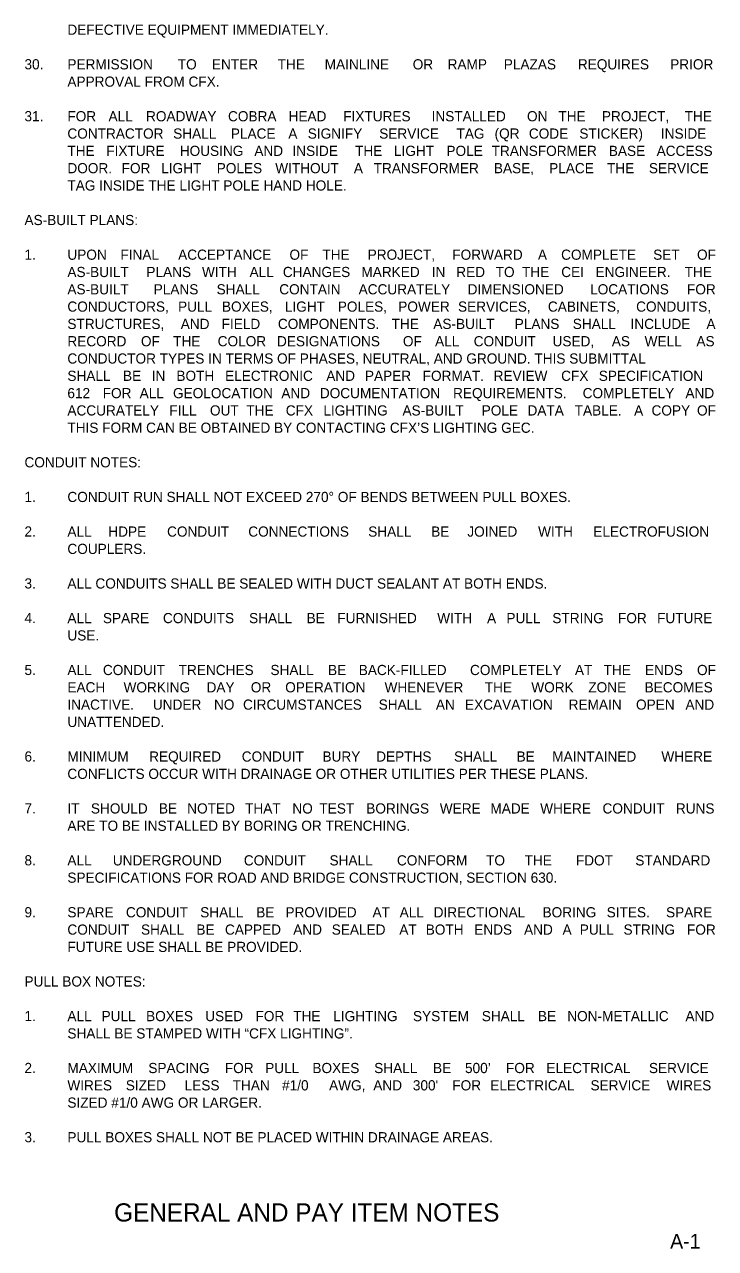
# Model space of a CAD drawing. Extents: x -55 to 2471539, y -90 to 3608906.
# Drawn here: x 1052 to 1526, y -64 to 777 of the extents above; entities that cross this region are included whole.
import ezdxf

# ---------------------------------------------------------------- set-up
doc = ezdxf.new("R2010")
doc.units = 0
for name, color, linetype in [('SheetLines_dp', 7, 'Continuous'), ('TextMisc', 7, 'Continuous'), ('XSCell', 7, 'Continuous')]:
    doc.layers.add(name, color=color, linetype=linetype)

msp = doc.modelspace()

# ---------------------------------------------------------------- texts
at = {"layer": 'SheetLines_dp'}
msp.add_text('A-1', height=10, dxfattribs=at).set_placement((1495.16, -64.49))
at = {"layer": 'TextMisc'}
msp.add_text('GENERAL AND PAY ITEM NOTES ', height=12.5, dxfattribs=at).set_placement((1113.09, -45.92))
at = {"layer": 'XSCell'}
for s, p in [('DEFECTIVE EQUIPMENT IMMEDIATELY.', (1080.99, 770.14)), ('30.', (1051.5, 746.38)), ('PERMISSION ', (1080.99, 746.34)), ('TO ', (1156.84, 746.34)), ('ENTER ', (1180.3, 746.34)), ('THE ', (1225.48, 746.34)), ('MAINLINE ', (1257.78, 746.34)), ('OR ', (1318.26, 746.34)), ('RAMP ', (1342.22, 746.34)), ('PLAZAS ', (1380.82, 746.34)), ('REQUIRES ', (1431.73, 746.34)), ('PRIOR ', (1495.16, 746.34)), ('APPROVAL FROM CFX.', (1080.99, 734.44)), ('31.', (1051.5, 710.68)), ('FOR ', (1080.99, 710.64)), ('ALL ', (1109.24, 710.64)), ('ROADWAY ', (1135.03, 710.64)), ('COBRA ', (1191.36, 710.64)), ('HEAD ', (1232.94, 710.64)), ('FIXTURES ', (1270.52, 710.64)), ('INSTALLED ', (1331.24, 710.64)), ('ON ', (1396.78, 710.64)), ('THE ', (1418.36, 710.64)), ('PROJECT, ', (1448.22, 710.64)), ('THE ', (1505.1, 710.64)), ('CONTRACTOR ', (1080.99, 698.74)), ('SHALL ', (1153.67, 698.74)), ('PLACE ', (1193.29, 698.74)), ('A ', (1232.77, 698.74)), ('SIGNIFY ', (1246.14, 698.74)), ('SERVICE ', (1295.23, 698.74)), ('TAG ', (1348.34, 698.74)), ('(QR ', (1374.5, 698.74)), ('CODE ', (1398.05, 698.74)), ('STICKER) ', (1432.76, 698.74)), ('INSIDE ', (1488.78, 698.74)), ('THE ', (1080.99, 686.84)), ('FIXTURE ', (1107.71, 686.84)), ('HOUSING ', (1158.21, 686.84)), ('AND ', (1209.44, 686.84)), ('INSIDE ', (1235.62, 686.84)), ('THE ', (1278.65, 686.84)), ('LIGHT ', (1305.37, 686.84)), ('POLE ', (1341.43, 686.84)), ('TRANSFORMER ', (1372.49, 686.84)), ('BASE ', (1453, 686.84)), ('ACCESS ', (1485.85, 686.84)), ('DOOR. ', (1080.99, 674.94)), ('FOR ', (1118.27, 674.94)), ('LIGHT ', (1145.44, 674.94)), ('POLES ', (1183.59, 674.94)), ('WITHOUT ', (1223.8, 674.94)), ('A ', (1277.8, 674.94)), ('TRANSFORMER ', (1291.42, 674.94)), ('BASE, ', (1374.02, 674.94)), ('PLACE ', (1412, 674.94)), ('THE ', (1451.74, 674.94)), ('SERVICE ', (1480.54, 674.94)), ('TAG INSIDE THE LIGHT POLE HAND HOLE.', (1080.99, 663.04)), ('AS-BUILT PLANS:', (1051.5, 639.28)), ('1.', (1051.5, 615.48)), ('UPON ', (1080.99, 615.44)), ('FINAL ', (1117.41, 615.44)), ('ACCEPTANCE ', (1157.09, 615.44)), ('OF ', (1233.58, 615.44)), ('THE ', (1256.2, 615.44)), ('PROJECT, ', (1287.31, 615.44)), ('FORWARD ', (1345.45, 615.44)), ('A ', (1404.28, 615.44)), ('COMPLETE ', (1420.22, 615.44)), ('SET ', (1483.47, 615.44)), ('OF ', (1513.59, 615.44)), ('AS-BUILT ', (1080.99, 603.54)), ('PLANS ', (1135.26, 603.54)), ('WITH ', (1173.46, 603.54)), ('ALL ', (1206.16, 603.54)), ('CHANGES ', (1229.03, 603.54)), ('MARKED ', (1283, 603.54)), ('IN ', (1331.35, 603.54)), ('RED ', (1348.18, 603.54)), ('TO ', (1375.25, 603.54)), ('THE ', (1393.35, 603.54)), ('CEI ', (1420.3, 603.54)), ('ENGINEER. ', (1443.89, 603.54)), ('THE ', (1505.1, 603.54)), ('AS-BUILT ', (1080.99, 591.64)), ('PLANS ', (1140.28, 591.64)), ('SHALL ', (1183.52, 591.64)), ('CONTAIN ', (1226.56, 591.64)), ('ACCURATELY ', (1281.08, 591.64)), ('DIMENSIONED ', (1355.99, 591.64)), ('LOCATIONS ', (1440.14, 591.64)), ('FOR ', (1506.71, 591.64)), ('CONDUCTORS, ', (1080.99, 579.74)), ('PULL ', (1157.04, 579.74)), ('BOXES, ', (1187.18, 579.74)), ('LIGHT ', (1230.39, 579.74)), ('POLES, ', (1266.78, 579.74)), ('POWER ', (1308.31, 579.74)), ('SERVICES, ', (1349.37, 579.74)), ('CABINETS, ', (1411.13, 579.74)), ('CONDUITS, ', (1471.76, 579.74)), ('STRUCTURES, ', (1080.99, 567.84)), ('AND ', (1158.87, 567.84)), ('FIELD ', (1186.95, 567.84)), ('COMPONENTS. ', (1225.61, 567.84)), ('THE ', (1303.77, 567.84)), ('AS-BUILT ', (1332.39, 567.84)), ('PLANS ', (1388.33, 567.84)), ('SHALL ', (1428.22, 567.84)), ('INCLUDE ', (1467.92, 567.84)), ('A ', (1520.06, 567.84)), ('RECORD ', (1080.99, 555.94)), ('OF ', (1131.52, 555.94)), ('THE ', (1153.64, 555.94)), ('COLOR ', (1184.25, 555.94)), ('DESIGNATIONS ', (1225, 555.94)), ('OF ', (1311.51, 555.94)), ('ALL ', (1333.62, 555.94)), ('CONDUIT ', (1360.16, 555.94)), ('USED, ', (1414.35, 555.94)), ('AS ', (1455.05, 555.94)), ('WELL ', (1477.57, 555.94)), ('AS ', (1513.18, 555.94)), ('CONDUCTOR TYPES IN TERMS OF PHASES, NEUTRAL, AND GROUND. THIS SUBMITTAL ', (1080.99, 544.04)), ('SHALL ', (1080.99, 532.14)), ('BE ', (1119.17, 532.14)), ('IN ', (1138.91, 532.14)), ('BOTH ', (1155.9, 532.14)), ('ELECTRONIC ', (1189.32, 532.14)), ('AND ', (1258.87, 532.14)), ('PAPER ', (1285.43, 532.14)), ('FORMAT. ', (1325.11, 532.14)), ('REVIEW ', (1373.87, 532.14)), ('CFX ', (1420.25, 532.14)), ('SPECIFICATION ', (1446.08, 532.14)), ('612 ', (1080.99, 520.24)), ('FOR ', (1105.26, 520.24)), ('ALL ', (1130.64, 520.24)), ('GEOLOCATION ', (1153.56, 520.24)), ('AND ', (1227.99, 520.24)), ('DOCUMENTATION ', (1254.44, 520.24)), ('REQUIREMENTS. ', (1345.98, 520.24)), ('COMPLETELY ', (1435.03, 520.24)), ('AND ', (1505.64, 520.24)), ('ACCURATELY ', (1080.99, 508.34)), ('FILL ', (1151.05, 508.34)), ('OUT ', (1178.93, 508.34)), ('THE ', (1203.92, 508.34)), ('CFX ', (1231.04, 508.34)), ('LIGHTING ', (1256.88, 508.34)), ('AS-BUILT ', (1311.22, 508.34)), ('POLE ', (1365.65, 508.34)), ('DATA ', (1397.11, 508.34)), ('TABLE. ', (1429.54, 508.34)), ('A ', (1470.38, 508.34)), ('COPY ', (1482.33, 508.34)), ('OF ', (1513.59, 508.34)), ('THIS FORM CAN BE OBTAINED BY CONTACTING CFX’S LIGHTING GEC.', (1080.99, 496.44)), ('CONDUIT NOTES:', (1051.5, 472.68)), ('1.', (1051.5, 448.88)), ('CONDUIT RUN SHALL NOT EXCEED 270° OF BENDS BETWEEN PULL BOXES.', (1080.99, 448.84)), ('2.', (1051.5, 425.08)), ('ALL ', (1080.99, 425.04)), ('HDPE ', (1109.12, 425.04)), ('CONDUIT ', (1149.48, 425.04)), ('CONNECTIONS ', (1205.26, 425.04)), ('SHALL ', (1287.67, 425.04)), ('BE ', (1330.94, 425.04)), ('JOINED ', (1355.77, 425.04)), ('WITH ', (1404.4, 425.04)), ('ELECTROFUSION ', (1442.34, 425.04)), ('COUPLERS.', (1080.99, 413.14)), ('3.', (1051.5, 389.38)), ('ALL CONDUITS SHALL BE SEALED WITH DUCT SEALANT AT BOTH ENDS.', (1080.99, 389.34)), ('4.', (1051.5, 365.58)), ('ALL ', (1080.99, 365.54)), ('SPARE ', (1105.4, 365.54)), ('CONDUITS ', (1146.66, 365.54)), ('SHALL ', (1205.81, 365.54)), ('BE ', (1245.36, 365.54)), ('FURNISHED ', (1266.47, 365.54)), ('WITH ', (1335.1, 365.54)), ('A ', (1369.33, 365.54)), ('PULL ', (1382.64, 365.54)), ('STRING ', (1414.2, 365.54)), ('FOR ', (1459.3, 365.54)), ('FUTURE ', (1486.16, 365.54)), ('USE.', (1080.99, 353.64)), ('5.', (1051.5, 329.88)), ('ALL ', (1080.99, 329.84)), ('CONDUIT ', (1105.4, 329.84)), ('TRENCHES ', (1157.46, 329.84)), ('SHALL ', (1220.52, 329.84)), ('BE ', (1260.08, 329.84)), ('BACK-FILLED ', (1281.18, 329.84)), ('COMPLETELY ', (1357.62, 329.84)), ('AT ', (1429.7, 329.84)), ('THE ', (1449.39, 329.84)), ('ENDS ', (1477.86, 329.84)), ('OF ', (1513.59, 329.84)), ('EACH ', (1080.99, 317.94)), ('WORKING ', (1119.56, 317.94)), ('DAY ', (1176.58, 317.94)), ('OR ', (1207.01, 317.94)), ('OPERATION ', (1230.64, 317.94)), ('WHENEVER ', (1298.91, 317.94)), ('THE ', (1367.77, 317.94)), ('WORK ', (1399.74, 317.94)), ('ZONE ', (1438.89, 317.94)), ('BECOMES ', (1477.59, 317.94)), ('INACTIVE. ', (1080.99, 306.04)), ('UNDER ', (1139.72, 306.04)), ('NO ', (1181.71, 306.04)), ('CIRCUMSTANCES ', (1201.67, 306.04)), ('SHALL ', (1294.86, 306.04)), ('AN ', (1334.17, 306.04)), ('EXCAVATION ', (1354.17, 306.04)), ('REMAIN ', (1425.41, 306.04)), ('OPEN ', (1471.68, 306.04)), ('AND ', (1505.64, 306.04)), ('UNATTENDED. ', (1080.99, 294.14)), ('6.', (1051.5, 270.38)), ('MINIMUM ', (1080.99, 270.34)), ('REQUIRED ', (1137.17, 270.34)), ('CONDUIT ', (1200.79, 270.34)), ('BURY ', (1256.25, 270.34)), ('DEPTHS ', (1293.15, 270.34)), ('SHALL ', (1346.65, 270.34)), ('BE ', (1389.61, 270.34)), ('MAINTAINED ', (1414.12, 270.34)), ('WHERE ', (1489.11, 270.34)), ('CONFLICTS OCCUR WITH DRAINAGE OR OTHER UTILITIES PER THESE PLANS.', (1080.99, 258.44)), ('7.', (1051.5, 234.68)), ('IT ', (1080.99, 234.64)), ('SHOULD ', (1097.15, 234.64)), ('BE ', (1143.86, 234.64)), ('NOTED ', (1163.32, 234.64)), ('THAT ', (1203.08, 234.64)), ('NO ', (1235.56, 234.64)), ('TEST ', (1254.12, 234.64)), ('BORINGS ', (1286.34, 234.64)), ('WERE ', (1336.87, 234.64)), ('MADE ', (1371.62, 234.64)), ('WHERE ', (1405.84, 234.64)), ('CONDUIT ', (1448.66, 234.64)), ('RUNS ', (1499.08, 234.64)), ('ARE TO BE INSTALLED BY BORING OR TRENCHING. ', (1080.99, 222.74)), ('8.', (1051.5, 198.98)), ('ALL ', (1080.99, 198.94)), ('UNDERGROUND ', (1112.19, 198.94)), ('CONDUIT ', (1202.21, 198.94)), ('SHALL ', (1261.07, 198.94)), ('CONFORM ', (1307.42, 198.94)), ('TO ', (1368.66, 198.94)), ('THE ', (1395.1, 198.94)), ('FDOT ', (1430.37, 198.94)), ('STANDARD ', (1471.21, 198.94)), ('SPECIFICATIONS FOR ROAD AND BRIDGE CONSTRUCTION, SECTION 630.', (1080.99, 187.04)), ('9.', (1051.5, 163.28)), ('SPARE ', (1080.99, 163.24)), ('CONDUIT ', (1121.21, 163.24)), ('SHALL ', (1172.23, 163.24)), ('BE ', (1210.74, 163.24)), ('PROVIDED ', (1230.81, 163.24)), ('AT ', (1290.64, 163.24)), ('ALL ', (1309.28, 163.24)), ('DIRECTIONAL ', (1332.64, 163.24)), ('BORING ', (1407.45, 163.24)), ('SITES. ', (1451.51, 163.24)), ('SPARE ', (1492.31, 163.24)), ('CONDUIT ', (1080.99, 151.34)), ('SHALL ', (1131.57, 151.34)), ('BE ', (1169.63, 151.34)), ('CAPPED ', (1189.25, 151.34)), ('AND ', (1236.18, 151.34)), ('SEALED ', (1262.62, 151.34)), ('AT ', (1309.03, 151.34)), ('BOTH ', (1327.22, 151.34)), ('ENDS ', (1360.52, 151.34)), ('AND ', (1394.76, 151.34)), ('A ', (1421.21, 151.34)), ('PULL ', (1433.03, 151.34)), ('STRING ', (1463.1, 151.34)), ('FOR ', (1506.71, 151.34)), ('FUTURE USE SHALL BE PROVIDED.', (1080.99, 139.44)), ('PULL BOX NOTES:', (1051.5, 115.68)), ('1.', (1051.5, 91.88)), ('ALL ', (1080.99, 91.84)), ('PULL ', (1104.45, 91.84)), ('BOXES ', (1135.06, 91.84)), ('USED ', (1175.69, 91.84)), ('FOR ', (1210.24, 91.84)), ('THE ', (1236.14, 91.84)), ('LIGHTING ', (1263.67, 91.84)), ('SYSTEM ', (1318.42, 91.84)), ('SHALL ', (1365.69, 91.84)), ('BE ', (1404.29, 91.84)), ('NON-METALLIC ', (1424.44, 91.84)), ('AND ', (1505.64, 91.84)), ('SHALL BE STAMPED WITH “CFX LIGHTING”.', (1080.99, 79.94)), ('2. ', (1051.5, 56.18)), ('MAXIMUM ', (1080.99, 56.14)), ('SPACING ', (1136.61, 56.14)), ('FOR ', (1189.17, 56.14)), ('PULL ', (1216.9, 56.14)), ('BOXES ', (1249.33, 56.14)), ('SHALL ', (1291.78, 56.14)), ('BE ', (1332.21, 56.14)), ('500’ ', (1354.18, 56.14)), ('FOR ', (1382.36, 56.14)), ('ELECTRICAL ', (1410.09, 56.14)), ('SERVICE ', (1480.54, 56.14)), ('WIRES ', (1080.99, 44.24)), ('SIZED ', (1121.12, 44.24)), ('LESS ', (1161.57, 44.24)), ('THAN ', (1194.55, 44.24)), ('#1/0 ', (1228.5, 44.24)), ('AWG, ', (1260.78, 44.24)), ('AND ', (1291.16, 44.24)), ("300' ", (1318.35, 44.24)), ('FOR ', (1345.46, 44.24)), ('ELECTRICAL ', (1371.58, 44.24)), ('SERVICE ', (1440.41, 44.24)), ('WIRES ', (1492.7, 44.24)), ('SIZED #1/0 AWG OR LARGER. ', (1080.99, 32.34)), ('3.', (1051.5, 8.58)), ('PULL BOXES SHALL NOT BE PLACED WITHIN DRAINAGE AREAS.', (1080.99, 8.54))]:
    msp.add_text(s, height=7, dxfattribs=at).set_placement(p)

doc.saveas('drawing.dxf')
